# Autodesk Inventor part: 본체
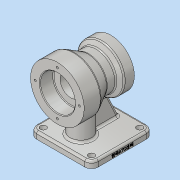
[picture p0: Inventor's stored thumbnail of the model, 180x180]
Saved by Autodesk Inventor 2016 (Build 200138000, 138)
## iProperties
Created: 2019-01
Part Number: 본체
Material: 알루미늄 6061
Document SubType Name: Modeling
Designer: MIRAE
Density: 2.7 g/cm^3
Appearance: 알루미늄 - 평지
Mass: 898.816 g
Surface Area: 600.964 cm^2
Volume: 332.895 cm^3
Author: MIRAE
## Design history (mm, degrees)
sketch "스케치1"
  geometry: L1 (-154.002, 80)-(171.9, 80); L2 (-46, 80)-(-46, 120); L3 (-46, 120)-(-21, 120); L4 (-0.215, 108)-(13.126, 108); L5 (13.126, 108)-(19, 115); L6 (19, 115)-(34, 115); L7 (34, 115)-(34, 80); L8 (-0.215, 108)-(-21, 120); 1 further point
  constraints: 16 end point, 2 parallel, 2 perpendicular, 2 point on line, 1 horizontal, 1 vertical
  dimensions: "d0" = 80 distance from line of L1 point (0, 0); "d1" = 25 distance of L2.end L3.end; "d2" = 15 distance of L5.end L6.end; "d5" = 50 deg angle of L4 L5; "d6" = 30 deg angle of L4 L8; "d7" = 56 diameter of L4 L1; "d8" = 80 diameter of L3 L1; "d9" = 70 diameter of L6 L1; "d10" = 80 distance between parallel lines of L7 L2; "d11" = 46 distance from line of L2 point (0, 0)
revolve "회전1" sketch "스케치1" stored, may be unused: angle "d12" = 90 deg
sketch "스케치2"
  geometry: L1 (-46, -41)-(46, -41); L2 (46, -41)-(46, 51); L3 (46, 51)-(-46, 51); L4 (-46, 51)-(-46, -41); L5 (-46, -41)-(46, 51); L6 (46, -41)-(-46, 51); L7 (40, -46)-(-40, -46) reference; 2 further points
  constraints: 12 end point, 2 midpoint, 2 parallel, 1 horizontal, 1 perpendicular
  dimensions: "d13" = 92 distance of L3.end L2.end; "d14" = 92 distance of L2.end L1.end; "d16" = 46 distance from line of L4 point (0, 0); "d116" = 5 distance from line of L1.start L7
extrude "돌출1" join sketch "스케치2" distance "d17" = 10; taper "d18" = 0 deg
sketch "스케치3"
  geometry: L1 (-46, -41)-(46, -41) reference; L2 (-46, 51)-(-46, -41) reference; C1 r 16 at (0, -11); 1 further point
  constraints: 1 centre point
  dimensions: "d19" = 16 radius of C1; "d20" = 30 distance from line of L1 C1.centre; "d21" = 46 distance from line of L2 C1.centre
extrude "돌출2" join sketch "스케치3" stored distance "d22" = 10; taper "d23" = 0 deg
sketch "스케치4"
  geometry: L1 (-5, -5)-(5, -5); L2 (5, -5)-(5, 5); L3 (5, 5)-(-5, 5); L4 (-5, 5)-(-5, -5); L5 (-5, -5)-(5, 5); L6 (5, -5)-(-5, 5); 2 further points
  constraints: 12 end point, 3 midpoint, 2 parallel, 1 coincident, 1 horizontal, 1 perpendicular
  dimensions: "d24" = 10 distance of L3.end L2.end; "d25" = 10 distance of L2.end L1.end
extrude "돌출3" join sketch "스케치4" stored distance "d26" = 10; taper "d27" = 0 deg
sketch "스케치5"
  geometry: L1 (41, 10)-(25.17, 43.947); L2 (51, 0)-(51, 10) reference; L3 (-41, 10)-(51, 10) reference; 1 further point
  constraints: 2 end point, 1 point on line
  dimensions: "d28" = 10 distance from line of L2 L1.start; "d30" = 25 deg angle of L1 L2
feature "리브1" sketch "스케치5" dims "d31" = 1, "d32" = 10, "d33" = 0, "d34" = 0, "d35" = 1, "d36" = 1
sketch "스케치6"
  geometry: L1 (-71.82, 80)-(72.262, 80); L2 (-41, 0)-(51, 0) reference; L3 (-46, 40)-(-46, 120) reference; L4 (-46, 80)-(-46, 106); L5 (-26, 106)-(-26, 96); L6 (-26, 96)-(17, 96); L7 (17, 96)-(17, 100); L8 (17, 100)-(34, 100); L9 (34, 45)-(34, 115) reference; L10 (-26, 106)-(-46, 106); L11 (-46, 80)-(34, 80); 1 further point
  constraints: 16 end point, 3 perpendicular, 2 horizontal, 2 midpoint, 2 point on line, 1 vertical
  dimensions: "d37" = 80 distance between parallel lines of L2 L1; "d38" = 20 distance of L5.start L4.end; "d39" = 17 distance of L7.end L8.end; "d40" = 52 diameter of L10 L1; "d41" = 32 diameter of L6 L1; "d42" = 40 diameter of L8 L1
revolve "회전2" sketch "스케치6" stored, may be unused: angle "d43" = 90 deg
fillet "모깎기1" dims "d44" = 10
sketch "스케치7"
  geometry: C1 r 26 at (0, 0) reference; 2 further points
  constraints: 1 vertical alignment
  dimensions: "d45" = 33 distance of C1.centre point (0, 33)
hole "구멍1" sketch "스케치7" at (0, 33) diameter "d46" = 3.242; stored, may be unused: countersink angle "d50" = 90 deg, drill point angle "d52" = 118 deg; dims "d47" = 9, "d48" = 4, "d49" = 2, "d51" = 11
sketch "스케치8"
  geometry: C1 r 20 at (0, 0) reference; A1 r 28 centre (0, 0) between (-5, 27.55) and (5, 27.55) reference; 2 further points
  constraints: 1 vertical alignment
  dimensions: "d56" = 27.5 distance of C1.centre point (0, -27.5)
hole "구멍2" sketch "스케치8" at (0, -27.5) diameter "d57" = 3.242; stored, may be unused: countersink angle "d61" = 90 deg, drill point angle "d63" = 118 deg; dims "d58" = 9, "d59" = 4, "d60" = 2, "d62" = 11
hole "구멍3" diameter "d69" = 9; stored, may be unused: countersink angle "d73" = 90 deg, drill point angle "d75" = 118 deg; dims "d67" = 10, "d68" = 10, "d70" = 9, "d71" = 4, "d72" = 2, "d74" = 11
hole "구멍4" diameter "d78" = 9; stored, may be unused: countersink angle "d82" = 90 deg, drill point angle "d84" = 118 deg; dims "d76" = 10, "d77" = 10, "d79" = 9, "d80" = 4, "d81" = 2, "d83" = 11
hole "구멍5" diameter "d87" = 9; stored, may be unused: countersink angle "d91" = 90 deg, drill point angle "d93" = 118 deg; dims "d85" = 10, "d86" = 10, "d88" = 9, "d89" = 4, "d90" = 2, "d92" = 11
hole "구멍6" diameter "d96" = 9; stored, may be unused: countersink angle "d100" = 90 deg, drill point angle "d102" = 118 deg; dims "d94" = 10, "d95" = 10, "d97" = 9, "d98" = 4, "d99" = 2, "d101" = 11
sketch "스케치9"
  geometry: L1 (0, 0)-(0, 72) reference; L2 (-10, -10)-(0, -10) reference; 3 further points
  constraints: 1 midpoint, 1 other
  dimensions: "d103" = 4 distance from line of L1 point (-4, 36); "d117" = 46 distance from line of point (-4, 36) L2
feature "엠보싱1" sketch "스케치9" dims "d0" = 80, "d1" = 25, "d2" = 15, "d5" = 50 deg, "d6" = 30 deg, "d7" = 56, "d8" = 80, "d9" = 70, "d10" = 80, "d11" = 46, "d104" = 0.5, "d105" = 0
fillet "모깎기2" dims "d106" = 3
fillet "모깎기3" dims "d107" = 3
fillet "모깎기4" dims "d108" = 3
fillet "모깎기5" dims "d109" = 3
fillet "모깎기6" dims "d110" = 3
fillet "모깎기7" dims "d111" = 1
fillet "모깎기8" dims "d112" = 0.6
chamfer "모따기1" distance "d113" = 1; stored, may be unused: second distance "d114" = 2, angle "d115" = 45 deg
feature "분할1"
node "솔리드1"
pattern_circular "원형 패턴1" dims angle "d54" = 360 deg
pattern_circular "원형 패턴2" dims angle "d65" = 360 deg
